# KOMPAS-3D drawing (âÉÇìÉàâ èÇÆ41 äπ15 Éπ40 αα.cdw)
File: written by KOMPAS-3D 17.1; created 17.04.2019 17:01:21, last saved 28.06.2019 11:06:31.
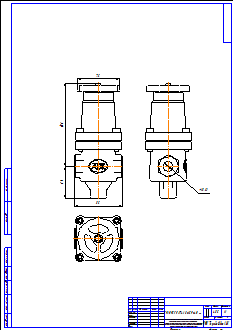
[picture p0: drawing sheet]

Sheet 1: A2, portrait

Title block, sheet 1: name: ГРАНРЕГ КАТ41 Ду15 Ру40 рр; material: Внимание! Данный продукт является объектом авторского права ООО «Торговый Дом АДЛ». / Запрещается изменение, копирование, распространение / (в том числе путем копирования на другие сайты и ресурсы в Интернете) / или любое иное использование информации и объектов без предварительного / согласия правообладателя (ООО «Торговый Дом АДЛ»).; mass: 4,85; sheets: 1; organisation: ООО "Торговый дом АДЛ"; sheet format: A2; stored path: \\adlc.lan\data\АДЛ_ПКД\3D-модели\ADL production\Клапаны КАТ ГРАНРЕГ\КАТ41\KOMPAS 2D\ГРАНРЕГ КАТ41 Ду15 Ру40 рр.cdw

Views: Вид 1, Проекционный вид 2, Проекционный вид 3
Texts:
  user
Dimensions and other numbers on the sheet: 85; 150; 57; 75; 18,63; 1:1; 1; 4,85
